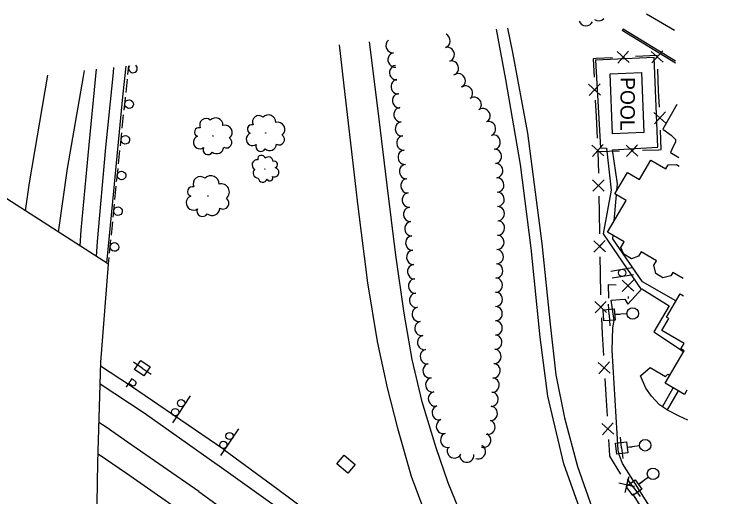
# Model space of a CAD drawing. Extents: x 1746010 to 1754829, y 655801 to 663091.
# Drawn here: x 1754024.1 to 1754523, y 657230 to 657566 of the extents above; entities that cross this region are included whole.
import ezdxf

# ---------------------------------------------------------------- set-up
doc = ezdxf.new("R2010")
doc.units = 0
for name, color, linetype in [('SURVEY - AERIAL SURVEY - Photo Control - Points - Elevations', 7, 'Continuous'), ('SURVEY - AERIAL SURVEY - Photo Control - Points - Locators', 7, 'Continuous'), ('SURVEY - AERIAL SURVEY - Photo Control - Points - Numbers', 7, 'Continuous'), ('SURVEY - AERIAL SURVEY - Photo Control with Text', 7, 'Continuous'), ('SURVEY - CENTERLINE - Existing Roads - Development', 7, 'Continuous'), ('SURVEY - CENTERLINE - Existing Roads Curve Text', 7, 'Continuous'), ('SURVEY - CENTERLINE - Existing Roads Text', 7, 'Continuous'), ('SURVEY - CENTERLINE - Preliminary - Development', 7, 'Continuous'), ('SURVEY - CONTROL - Points - Elevations', 7, 'Continuous')]:
    doc.layers.add(name, color=color, linetype=linetype)

msp = doc.modelspace()

# ---------------------------------------------------------------- linework, layer by layer
at = {"layer": 'SURVEY - AERIAL SURVEY - Photo Control - Points - Elevations'}
for points in [[(1754509.28, 657049.25), (1754522.98, 657070.16), (1754497.38, 657097.42), (1754470.31, 657128.36), (1754455.85, 657147.16), (1754440.71, 657172.61), (1754422.69, 657208.49), (1754406.86, 657253.02), (1754395.7, 657299.94), (1754390.43, 657341.04), (1754384.1, 657403.03), (1754376.62, 657461.49), (1754366.44, 657520.57), (1754359.92, 657555.6)], [(1754367.68, 657556.37), (1754370.98, 657539.33), (1754381.5, 657483.14), (1754391.36, 657406.41), (1754397.2, 657350.19), (1754401.25, 657314.92), (1754407.25, 657284.99), (1754416.42, 657251.03), (1754426.46, 657221.93)], [(1753982.28, 657188.73), (1754080.08, 657123.8), (1754080.93, 657167.72), (1754082.29, 657253.87), (1754084.25, 657323.66), (1754089.74, 657391.89), (1753986.12, 657458.37), (1753985.99, 657391.93), (1753985.12, 657295.57), (1753983.31, 657231.76)]]:
    msp.add_lwpolyline(points, dxfattribs=at)
at = {"layer": 'SURVEY - AERIAL SURVEY - Photo Control - Points - Locators'}
for points in [[(1754483.79, 657554.7), (1754464.4, 657566.02)], [(1754250.27, 657544.67), (1754254.34, 657510.19), (1754259.42, 657466.22), (1754263.31, 657432.04)], [(1754283.77, 657447.08), (1754277.31, 657500.58), (1754271.35, 657546.77)], [(1754101.85, 657529.87), (1754099.56, 657508.47), (1754093.23, 657442.89), (1754088.42, 657392.73)], [(1754054.84, 657414.28), (1754061.09, 657458.59), (1754072.18, 657522.73), (1754072.94, 657526.99)], [(1754081.18, 657527.81), (1754075.95, 657475.03), (1754070.47, 657415.62), (1754069.71, 657404.73)], [(1754081.34, 657397.27), (1754081.99, 657407.82), (1754087.85, 657473.31), (1754093.1, 657525.4), (1754093.53, 657529.04)], [(1754047.19, 657523.57), (1754034.39, 657448.62), (1754031.78, 657429.07)], [(1754485.58, 657503.22), (1754475.83, 657486.12), (1754481.63, 657481.93), (1754484.62, 657478.8), (1754484.55, 657476.91), (1754483.04, 657474.02), (1754481.09, 657469.86), (1754486.86, 657466.34)], [(1754336.85, 657213.49), (1754326.17, 657239.6), (1754317.84, 657263.97), (1754308.15, 657295.99), (1754301.07, 657325.53), (1754295.49, 657357.94), (1754289.9, 657398.27), (1754283.77, 657447.08)], [(1754263.31, 657432.04), (1754270.04, 657378.87), (1754276.75, 657338.19), (1754283.72, 657305.83), (1754290.96, 657277.73), (1754300.49, 657244.28), (1754311.09, 657215.71), (1754324.64, 657183.1), (1754338.91, 657154.83), (1754355.31, 657123.62), (1754374.99, 657091.81), (1754330.98, 657128), (1754283.23, 657165.86), (1754231.77, 657204.81), (1754165.2, 657252.52)], [(1754497.24, 657174.76), (1754447.65, 657253.07), (1754445.54, 657258.72), (1754444.52, 657262.5), (1754440.38, 657331.97), (1754440.89, 657347.55), (1754441.93, 657352.69), (1754439.66, 657366.99), (1754449.38, 657367.61), (1754451.29, 657364.02), (1754461.03, 657374.72), (1754480.11, 657362.98), (1754469.36, 657344.8), (1754490.22, 657331.13)], [(1754170.11, 657262.81), (1754105.13, 657307.2), (1754084.17, 657320.86)], [(1754460.23, 657314.3), (1754467.03, 657319.93), (1754477.7, 657313.71), (1754479.22, 657315.44), (1754480.58, 657314.7)], [(1754493.24, 657283.31), (1754487.19, 657286.15), (1754479.05, 657290.32), (1754473.35, 657294.05), (1754467.91, 657299.95), (1754463.9, 657305.68), (1754460.23, 657314.3)], [(1754083.82, 657308.56), (1754114.44, 657288.32), (1754165.29, 657252.46)], [(1754152.65, 657233.59), (1754102.91, 657267.95), (1754088.18, 657278.44), (1754083.07, 657281.81)], [(1754082.46, 657259.82), (1754102.35, 657246.49), (1754133.89, 657224.33)], [(1754170.11, 657262.81), (1754207.54, 657235.31), (1754247.49, 657205.62), (1754270.97, 657185.18), (1754322.72, 657143.88), (1754349.35, 657124.09), (1754354.76, 657124.68)], [(1754152.65, 657233.59), (1754205.11, 657195.65)]]:
    msp.add_lwpolyline(points, dxfattribs=at)
at = {"layer": 'SURVEY - AERIAL SURVEY - Photo Control - Points - Numbers'}
for points in [[(1754484.53, 657533.45), (1754448.07, 657555.73), (1754447.48, 657554.78)], [(1754484.57, 657532.11), (1754447.48, 657554.78)], [(1754103.28, 657524.09), (1754103.93, 657530.08)], [(1754102.42, 657516.24), (1754102.93, 657520.91)], [(1754101.91, 657511.57), (1754102.42, 657516.24)], [(1754100.59, 657499.24), (1754101.47, 657507.54), (1754101.56, 657508.39)], [(1754099.77, 657491.38), (1754100.26, 657496.06)], [(1754099.27, 657486.71), (1754099.77, 657491.38)], [(1754097.98, 657474.38), (1754098.94, 657483.53)], [(1754097.15, 657466.52), (1754097.64, 657471.2)], [(1754096.65, 657461.85), (1754097.15, 657466.52)], [(1754095.36, 657449.52), (1754095.46, 657450.54), (1754096.32, 657458.67)], [(1754094.59, 657441.65), (1754095.05, 657446.33)], [(1754094.14, 657436.98), (1754094.59, 657441.65)], [(1754092.93, 657424.63), (1754093.83, 657433.79)], [(1754092.17, 657416.77), (1754092.62, 657421.45)], [(1754091.71, 657412.09), (1754092.17, 657416.77)], [(1754090.51, 657399.75), (1754091.4, 657408.91)], [(1754089.74, 657391.89), (1754090.2, 657396.57)]]:
    msp.add_lwpolyline(points, dxfattribs=at)
for centre, start, end in [((1754106.73, 657528.29), 142.3212, 286.8748), ((1754106.73, 657528.29), 286.8888, 49.0648), ((1754104.03, 657503.45), 287.1092, 287.0952), ((1754101.42, 657478.59), 287.1092, 287.0952), ((1754098.8, 657453.73), 287.1092, 287.0952), ((1754096.34, 657428.88), 287.5636, 287.5496), ((1754093.91, 657403.99), 287.5636, 287.5496)]:
    msp.add_arc(centre, 3, start, end, dxfattribs=at)
at = {"layer": 'SURVEY - AERIAL SURVEY - Photo Control with Text'}
for p, q in [((1754439.64, 657387.09), (1754454.44, 657389.56)), ((1754440.43, 657382.36), (1754455.23, 657384.82)), ((1754146.49, 657300.22), (1754134.2, 657281.49)), ((1754180.32, 657277.2), (1754167.61, 657258.75))]:
    msp.add_line(p, q, dxfattribs=at)
for centre, radius in [((1754447.43, 657385.96), 2.54), ((1754140.25, 657295.17), 2.5), ((1754136.13, 657288.9), 2.5), ((1754173.96, 657272.29), 2.5), ((1754169.71, 657266.12), 2.5)]:
    msp.add_circle(centre, radius, dxfattribs=at)
at = {"layer": 'SURVEY - CENTERLINE - Existing Roads - Development'}
for points in [[(1754451.86, 657540.43), (1754444.38, 657532.04), (1754448.07, 657536.23), (1754452.27, 657532.44), (1754443.97, 657540.03)], [(1754476.06, 657532.58), (1754467.72, 657540.12), (1754471.89, 657536.4), (1754468.06, 657532.23), (1754475.71, 657540.47)], [(1754429.3, 657535.19), (1754427.2, 657535.08), (1754427.87, 657522.2)], [(1754443.78, 657443.4), (1754444.17, 657447.88), (1754440.65, 657471.53), (1754472.15, 657473.4), (1754469.69, 657535.95), (1754428.82, 657534.02), (1754432.36, 657473.09), (1754436.41, 657472.76), (1754439.7, 657443.43), (1754434.26, 657413.23), (1754460.71, 657374.37)], [(1754440.68, 657535.76), (1754429.3, 657535.19)], [(1754471.75, 657537.32), (1754456.76, 657536.57)], [(1754472.81, 657512.72), (1754472.16, 657527.7)], [(1754424.02, 657517.3), (1754432.42, 657509.82), (1754428.22, 657513.51), (1754432.01, 657517.71), (1754424.43, 657509.41)], [(1754473.31, 657501.33), (1754472.81, 657512.72)], [(1754428.71, 657506.13), (1754429.3, 657494.74)], [(1754429.3, 657494.74), (1754430.08, 657479.76)], [(1754477.9, 657490.12), (1754469.56, 657497.66), (1754473.73, 657493.94), (1754469.91, 657489.77), (1754477.56, 657498.01)], [(1754473.05, 657471.74), (1754474.59, 657471.79), (1754474.01, 657485.24)], [(1754426.24, 657474.85), (1754434.64, 657467.38), (1754430.44, 657471.07), (1754434.23, 657475.27), (1754426.65, 657466.96)], [(1754450.4, 657466.91), (1754458.04, 657475.16), (1754454.27, 657471.04), (1754450.14, 657474.91), (1754458.29, 657467.17)], [(1754430.58, 657470.37), (1754445.57, 657470.86)], [(1754430.58, 657470.37), (1754430.85, 657455.42)], [(1754461.66, 657471.38), (1754473.05, 657471.74)], [(1754489.8, 657382.08), (1754482.66, 657386.27), (1754481.29, 657383.93), (1754475.82, 657382.49), (1754470.8, 657385.43), (1754469.54, 657391.26), (1754471.34, 657394.32), (1754460.56, 657400.65), (1754458.77, 657397.6), (1754453.84, 657395.73), (1754448.5, 657398.87), (1754446.58, 657403.6), (1754448.89, 657407.54), (1754437.31, 657414.33), (1754450.21, 657436.31), (1754442.33, 657440.93), (1754451.13, 657455.94), (1754459.45, 657451.06), (1754467.31, 657464.47), (1754477.78, 657458.32), (1754479.46, 657461.18), (1754485.21, 657461.34), (1754487.08, 657460.24)], [(1754426.84, 657450.67), (1754434.98, 657442.93), (1754430.91, 657446.75), (1754434.84, 657450.81), (1754426.98, 657442.79)], [(1754431.15, 657439.38), (1754431.35, 657428.01)], [(1754441.95, 657422.23), (1754443.5, 657440.24)], [(1754431.35, 657428.01), (1754431.63, 657413.06)], [(1754484.89, 657366.38), (1754461.62, 657379.77), (1754440.86, 657409.68), (1754441.07, 657412.13)], [(1754427.61, 657408.31), (1754435.76, 657400.57), (1754431.69, 657404.39), (1754435.61, 657408.45), (1754427.76, 657400.43)], [(1754431.92, 657397.02), (1754432.13, 657385.66)], [(1754432.13, 657385.66), (1754432.41, 657370.7)], [(1754447.43, 657380.95), (1754455.49, 657373.11), (1754451.46, 657376.98), (1754455.43, 657381.01), (1754447.49, 657373.05)], [(1754438.21, 657368.33), (1754437.86, 657377.87), (1754443.31, 657377.7)], [(1754451.61, 657369.58), (1754451.62, 657368.07)], [(1754492.51, 657304.14), (1754490.82, 657301.25), (1754477.33, 657309.17), (1754490.53, 657331.66), (1754488.38, 657332.92), (1754490.6, 657336.69), (1754475.07, 657345.8), (1754479.95, 657354.11), (1754478.27, 657355.1), (1754487.85, 657371.42), (1754490.22, 657370.02)], [(1754428.39, 657365.95), (1754436.54, 657358.21), (1754432.47, 657362.03), (1754436.39, 657366.09), (1754428.54, 657358.07)], [(1754432.93, 657354.66), (1754433.6, 657343.3)], [(1754433.6, 657343.3), (1754434.48, 657328.35)], [(1754430.66, 657323.43), (1754439.11, 657316.03), (1754434.89, 657319.68), (1754438.65, 657323.9), (1754431.13, 657315.56)], [(1754435.42, 657312.31), (1754436.09, 657300.95)], [(1754475.53, 657292.63), (1754482.83, 657305.93)], [(1754436.09, 657300.95), (1754436.97, 657286.01)], [(1754486.39, 657303.85), (1754478.78, 657290.49)], [(1754433.15, 657281.09), (1754441.6, 657273.68), (1754437.38, 657277.33), (1754441.14, 657281.55), (1754433.62, 657273.22)], [(1754437.92, 657269.97), (1754438.58, 657258.61)], [(1754438.58, 657258.61), (1754438.61, 657258.22), (1754446.22, 657245.79)], [(1754445.17, 657239.66), (1754456.11, 657237.09), (1754450.67, 657238.33), (1754452, 657243.81), (1754449.29, 657232.94)], [(1754454.61, 657232.09), (1754460.55, 657222.39)]]:
    msp.add_lwpolyline(points, dxfattribs=at)
msp.add_lwpolyline([(1754460.85, 657525.44), (1754462.52, 657483.66), (1754440.65, 657482.79), (1754438.98, 657524.57)], close=True, dxfattribs=at)
at = {"layer": 'SURVEY - CENTERLINE - Existing Roads Curve Text'}
for p, q in [((1754438.3, 657356.63), (1754437.82, 657364.11)), ((1754438.3, 657356.63), (1754438.77, 657349.14)), ((1754450.87, 657357.42), (1754442.19, 657356.87)), ((1754442.59, 657356.9), (1754445.78, 657357.1)), ((1754113.24, 657319.52), (1754107.05, 657323.76)), ((1754113.24, 657319.52), (1754119.43, 657315.28)), ((1754447.03, 657263.96), (1754446.17, 657271.41)), ((1754459.54, 657265.4), (1754450.9, 657264.4)), ((1754451.3, 657264.45), (1754454.48, 657264.82)), ((1754447.03, 657263.96), (1754447.88, 657256.51)), ((1754455.61, 657236.2), (1754451.19, 657242.25)), ((1754465.78, 657243.64), (1754458.76, 657238.51)), ((1754459.08, 657238.74), (1754461.67, 657240.63)), ((1754455.61, 657236.2), (1754460.04, 657230.15))]:
    msp.add_line(p, q, dxfattribs=at)
for points in [[(1754434.16, 657360.27), (1754441.94, 657360.77), (1754442.44, 657352.98), (1754434.65, 657352.49)], [(1754112.22, 657324.94), (1754118.66, 657320.53), (1754114.25, 657314.1), (1754107.81, 657318.51)], [(1754442.7, 657267.39), (1754450.45, 657268.28), (1754451.35, 657260.53), (1754443.6, 657259.64)], [(1754450.16, 657237.05), (1754456.46, 657241.65), (1754461.06, 657235.36), (1754454.77, 657230.75)]]:
    msp.add_lwpolyline(points, close=True, dxfattribs=at)
for centre in [(1754454.77, 657357.67), (1754463.42, 657265.84), (1754468.93, 657245.95)]:
    msp.add_circle(centre, 4, dxfattribs=at)
at = {"layer": 'SURVEY - CENTERLINE - Existing Roads Text'}
for centre, radius in [((1754162.39, 657481.25), 0.157), ((1754199.14, 657483.34), 0.156), ((1754198.61, 657458.29), 0.11), ((1754158.93, 657439.51), 0.174)]:
    msp.add_circle(centre, radius, dxfattribs=at)
for centre, radius, start, end in [((1754194.45, 657490.95), 4.48, 49.4933, 206.2823), ((1754201.02, 657490.82), 5.1, 358.5461, 136.0703), ((1754157.67, 657488.9), 4.5, 49.4933, 206.2823), ((1754164.28, 657488.77), 5.13, 358.5461, 136.0703), ((1754207.46, 657485.8), 5.07, 309.4419, 105.2804), ((1754152.66, 657483.98), 3.09, 71.6095, 250.3551), ((1754170.75, 657483.73), 5.1, 309.4419, 105.2804), ((1754189.47, 657486.05), 3.07, 71.6095, 250.3551), ((1754153.28, 657476.89), 4.49, 111.6302, 305.0499), ((1754171.82, 657476.72), 3.76, 239.6948, 54.6951), ((1754190.08, 657479), 4.47, 111.6302, 305.0499), ((1754208.51, 657478.84), 3.74, 239.6948, 54.6951), ((1754195.71, 657473.87), 3.4, 154.2488, 331.568), ((1754201.82, 657475.92), 4.82, 229.5359, 356.3816), ((1754158.94, 657471.73), 3.42, 154.2488, 331.568), ((1754165.09, 657473.78), 4.84, 229.5359, 356.3816), ((1754193.26, 657461.2), 3.56, 84.4013, 240.2398), ((1754196.2, 657465.18), 2.62, 14.6542, 189.6544), ((1754200.97, 657463.3), 3.38, 4.4953, 131.3409), ((1754205.02, 657461.28), 2.39, 289.2082, 106.5274), ((1754193.96, 657455.52), 3.58, 133.5054, 271.0297), ((1754205.26, 657455.94), 3.13, 246.5895, 80.0092), ((1754153.69, 657448.01), 5, 49.4933, 206.2823), ((1754161.03, 657447.86), 5.69, 358.5461, 136.0703), ((1754197.16, 657452.19), 3.14, 184.4527, 341.2416), ((1754202.06, 657452.14), 2.16, 206.5689, 25.3145), ((1754148.12, 657442.54), 3.43, 71.6095, 250.3551), ((1754168.21, 657442.26), 5.66, 309.4419, 105.2804), ((1754148.81, 657434.67), 4.99, 111.6302, 305.0499), ((1754169.39, 657434.48), 4.17, 239.6948, 54.6951), ((1754155.09, 657428.94), 3.8, 154.2488, 331.568), ((1754161.92, 657431.22), 5.38, 229.5359, 356.3816)]:
    msp.add_arc(centre, radius, start, end, dxfattribs=at)
for centre, major_axis, start_param, end_param in [((1754422.06, 657562.77), (-4.59, 1.98), 0.738225, 3.141593), ((1754431.23, 657566.23), (-4.59, -1.99), 0.505287, 1.978697), ((1754322.87, 657547.63), (1.49, -4.77), 0, 2.402069), ((1754287.57, 657544.17), (-0.71, 4.95), 0.533719, 3.141593), ((1754288.99, 657534.27), (-0.71, 4.95), 0, 3.141593), ((1754325.84, 657538.09), (1.49, -4.77), 0, 3.141593), ((1754328.81, 657528.55), (1.49, -4.77), 0, 3.141593), ((1754290.1, 657525.4), (-0.51, 4.97), 0, 3.141593), ((1754333.44, 657519.82), (2.44, -4.36), 0, 3.141593), ((1754291.11, 657515.61), (-0.51, 4.97), 0, 3.141593), ((1754338.51, 657511.33), (3.05, -3.96), 0, 3.141593), ((1754292.11, 657505.83), (-0.51, 4.97), 0, 3.141593), ((1754344.59, 657503.43), (3.05, -3.96), 0, 3.141593), ((1754293.11, 657496.04), (-0.51, 4.97), 0, 3.141593), ((1754350.67, 657495.53), (3.05, -3.96), 0, 3.141593), ((1754294.12, 657486.25), (-0.51, 4.97), 0, 3.141593), ((1754354.59, 657486.42), (1.72, -4.7), 0, 3.141593), ((1754295.11, 657476.41), (-0.47, 4.98), 0, 3.141593), ((1754357.84, 657476.99), (0.44, -4.98), 0, 3.141593), ((1754296.05, 657466.45), (-0.47, 4.98), 0, 3.141593), ((1754358.71, 657467.05), (0.44, -4.98), 0, 3.141593), ((1754296.99, 657456.5), (-0.47, 4.98), 0, 3.141593), ((1754359.58, 657457.11), (0.44, -4.98), 0, 3.141593), ((1754297.94, 657446.54), (-0.47, 4.98), 0, 3.141593), ((1754360.36, 657447.16), (0.1, -5), 0, 3.141593), ((1754298.88, 657436.59), (-0.47, 4.98), 0, 3.141593), ((1754360.56, 657437.16), (0.1, -5), 0, 3.141593), ((1754299.82, 657426.63), (-0.47, 4.98), 0, 3.141593), ((1754360.76, 657427.17), (0.1, -5), 0, 3.141593), ((1754300.69, 657416.67), (-0.33, 4.99), 0, 3.141593), ((1754360.87, 657417.18), (-0.21, -5), 0, 3.141593), ((1754301.34, 657406.7), (-0.33, 4.99), 0, 3.141593), ((1754360.44, 657407.22), (-0.21, -5), 0, 3.141593), ((1754302, 657396.74), (-0.33, 4.99), 0, 3.141593), ((1754360.01, 657397.27), (-0.21, -5), 0, 3.141593), ((1754302.65, 657386.77), (-0.33, 4.99), 0, 3.141593), ((1754359.59, 657387.32), (-0.21, -5), 0, 3.141593), ((1754303.31, 657376.8), (-0.33, 4.99), 0, 3.141593), ((1754359.31, 657377.38), (-0.02, -5), 0, 3.141593), ((1754303.96, 657366.84), (-0.33, 4.99), 0, 3.141593), ((1754359.28, 657367.45), (-0.02, -5), 0, 3.141593), ((1754305.83, 657357.01), (-0.94, 4.91), 0, 3.141593), ((1754359.25, 657357.52), (-0.02, -5), 0, 3.141593), ((1754307.71, 657347.19), (-0.94, 4.91), 0, 3.141593), ((1754359.22, 657347.59), (-0.02, -5), 0, 3.141593), ((1754309.59, 657337.37), (-0.94, 4.91), 0, 3.141593), ((1754359.03, 657337.66), (-0.33, -4.99), 0, 3.141593), ((1754311.48, 657327.55), (-0.94, 4.91), 0, 3.141593), ((1754358.38, 657327.72), (-0.33, -4.99), 0, 3.141593), ((1754313.36, 657317.73), (-0.94, 4.91), 0, 3.141593), ((1754357.73, 657317.77), (-0.33, -4.99), 0, 3.141593), ((1754315.24, 657307.91), (-0.94, 4.91), 0, 3.141593), ((1754357.08, 657307.83), (-0.33, -4.99), 0, 3.141593), ((1754317.13, 657298.09), (-0.94, 4.91), 0, 3.141593), ((1754356.44, 657297.9), (-0.31, -4.99), 0, 3.141593), ((1754319.73, 657288.45), (-1.49, 4.77), 0, 3.141593), ((1754355.84, 657287.98), (-0.31, -4.99), 0, 3.141593), ((1754322.7, 657278.91), (-1.49, 4.77), 0, 3.141593), ((1754354.19, 657278.38), (-1.53, -4.76), 0, 3.141593), ((1754325.67, 657269.37), (-1.49, 4.77), 0, 3.141593), ((1754351.2, 657269.26), (-2.08, -4.55), 0, 3.141593), ((1754347.51, 657261.21), (-2.08, -4.55), 0, 3.141593), ((1754330.53, 657261.71), (-4.55, 2.08), 0, 3.141593), ((1754339.24, 657258.75), (-4.96, -0.66), 0, 3.141593)]:
    msp.add_ellipse(centre, major_axis=major_axis, ratio=0.940188, start_param=start_param, end_param=end_param, dxfattribs=at)
at = {"layer": 'SURVEY - CENTERLINE - Preliminary - Development'}
msp.add_line((1754255.05, 657252.7), (1754255.05, 657252.7), dxfattribs=at)
msp.add_lwpolyline([(1754248.65, 657252.89), (1754253.83, 657258.98), (1754261.45, 657252.51), (1754256.27, 657246.41), (1754248.65, 657252.89)], dxfattribs=at)

# ---------------------------------------------------------------- texts
at = {"layer": 'SURVEY - CENTERLINE - Existing Roads Curve Text'}
msp.add_text('P', height=7.48, rotation=325.5903, dxfattribs=at).set_placement((1754100.9, 657307))
at = {"layer": 'SURVEY - CONTROL - Points - Elevations'}
msp.add_text('POOL', height=10.001, rotation=269.8949, dxfattribs=at).set_placement((1754446.28, 657522.25))

doc.saveas('drawing.dxf')
